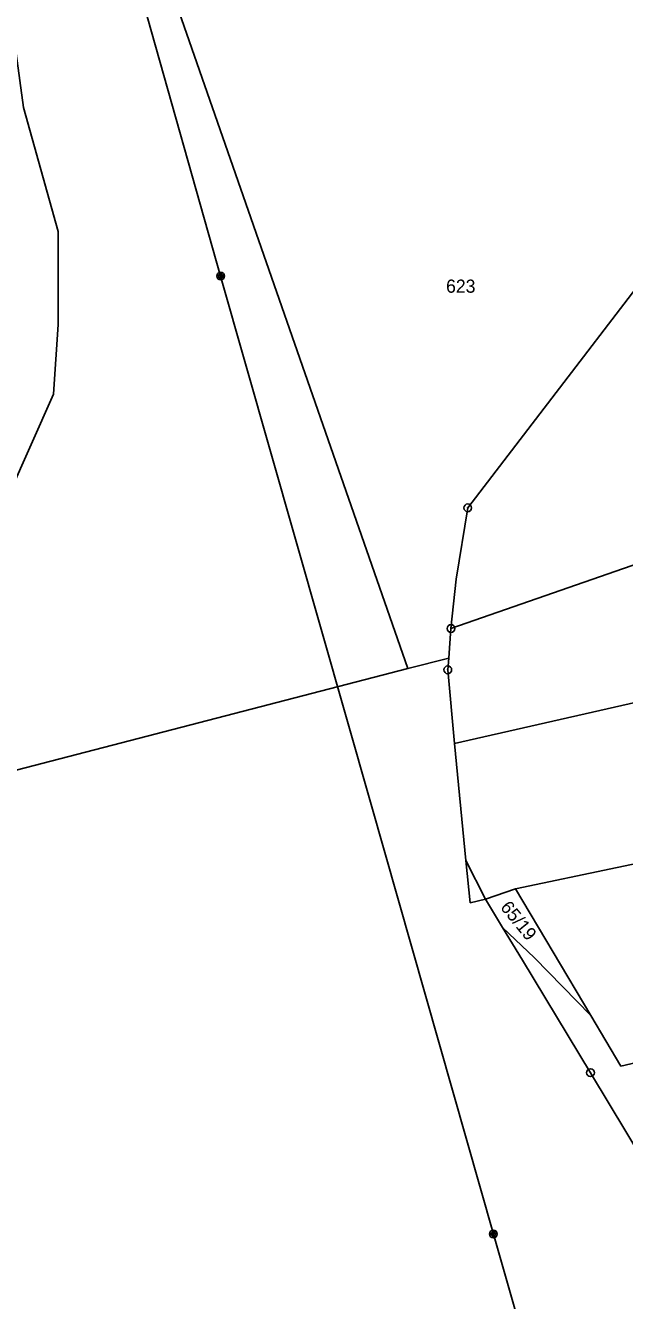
# Model space of a CAD drawing. Extents: x -725765 to -723182, y -1052705 to -1049154.
# Drawn here: x -725049.2 to -724971.9, y -1051081 to -1050916.4 of the extents above; entities that cross this region are included whole.
import ezdxf

# ---------------------------------------------------------------- set-up
doc = ezdxf.new("R2010")
doc.units = 0
for name, color, linetype in [('Vrstva 1', 7, 'Continuous'), ('Vrstva 12', 7, 'Continuous'), ('Vrstva 18', 7, 'Continuous'), ('Vrstva 25', 7, 'Continuous'), ('Vrstva 4', 7, 'Continuous'), ('Vrstva 52', 7, 'Continuous')]:
    doc.layers.add(name, color=color, linetype=linetype)

msp = doc.modelspace()

# ---------------------------------------------------------------- linework, layer by layer
at = {"layer": 'Vrstva 1'}
for points in [[(-725031.43, -1050908.84), (-724999.85, -1050999.45)], [(-724959.02, -1050935.48), (-724992.12, -1050978.69)], [(-724994.29, -1050994.27), (-724880.84, -1050954.87)], [(-724992.12, -1050978.69), (-724993.62, -1050987.89)], [(-724993.62, -1050987.89), (-724994.29, -1050994.27)], [(-724994.29, -1050994.27), (-724994.58, -1050998.09)], [(-724994.58, -1050998.09), (-724999.85, -1050999.45)], [(-724994.58, -1050998.09), (-724994.7, -1050999.6)], [(-724999.85, -1050999.45), (-725199.88, -1051051.31)], [(-724994.7, -1050999.6), (-724993.85, -1051009.11)], [(-724993.85, -1051009.11), (-724952.51, -1050999.73)], [(-724993.85, -1051009.11), (-724992.37, -1051024.21)], [(-724985.97, -1051027.89), (-724946.57, -1051019.61)], [(-724992.37, -1051024.21), (-724991.83, -1051029.69)], [(-724989.82, -1051029.22), (-724985.97, -1051027.89)], [(-724985.97, -1051027.89), (-724976.24, -1051044.24)], [(-724991.83, -1051029.69), (-724989.82, -1051029.22)], [(-724989.82, -1051029.22), (-724987.63, -1051032.85)], [(-724987.63, -1051032.85), (-724983.52, -1051036.79)], [(-724987.63, -1051032.85), (-724985.05, -1051037.1)], [(-724983.52, -1051036.79), (-724976.24, -1051044.24)], [(-724985.05, -1051037.1), (-724976.27, -1051051.61)], [(-724976.24, -1051044.24), (-724972.36, -1051050.76)], [(-724976.27, -1051051.61), (-724964.46, -1051071.2)], [(-724972.36, -1051050.76), (-724970.31, -1051050.31)]]:
    msp.add_lwpolyline(points, dxfattribs=at)
at = {"layer": 'Vrstva 12'}
for points in [[(-725043.92, -1050878.32), (-725024.03, -1050948.77)], [(-725024.03, -1050948.77), (-725004.59, -1051016.98)], [(-725004.59, -1051016.98), (-724988.81, -1051072.44)], [(-724973.47, -1051126.02), (-724988.81, -1051072.44)]]:
    msp.add_lwpolyline(points, dxfattribs=at)
at = {"layer": 'Vrstva 25'}
for centre, radius in [((-725024.03, -1050948.77), 0.5), ((-725024.03, -1050948.77), 0.3), ((-725024.03, -1050948.77), 0.15), ((-724992.12, -1050978.69), 0.5), ((-724992.12, -1050978.69), 0.032), ((-724994.29, -1050994.27), 0.5), ((-724994.29, -1050994.27), 0.032), ((-724994.7, -1050999.6), 0.5), ((-724994.7, -1050999.6), 0.032), ((-724976.27, -1051051.61), 0.5), ((-724976.27, -1051051.61), 0.032), ((-724988.81, -1051072.44), 0.5), ((-724988.81, -1051072.44), 0.3), ((-724988.81, -1051072.44), 0.15)]:
    msp.add_circle(centre, radius, dxfattribs=at)
at = {"layer": 'Vrstva 4'}
msp.add_lwpolyline([(-724992.37, -1051024.21), (-724989.82, -1051029.22)], dxfattribs=at)
at = {"layer": 'Vrstva 52'}
for points in [[(-725222.31, -1051084), (-725204.74, -1051077.08), (-725195.29, -1051073.36), (-725189.31, -1051071), (-725147.13, -1051053), (-725104.19, -1051030), (-725082.38, -1051016), (-725065.81, -1050999), (-725051.38, -1050977), (-725045.63, -1050964), (-725045, -1050955), (-725045, -1050943), (-725049.5, -1050927), (-725051.38, -1050913), (-725049.5, -1050902), (-725045, -1050886), (-725040.9, -1050880.49)], [(-725040.9, -1050880.49), (-725031.43, -1050908.84), (-724999.85, -1050999.45), (-724994.58, -1050998.09), (-724994.29, -1050994.27), (-724993.62, -1050987.89), (-724992.12, -1050978.69), (-724959.02, -1050935.48), (-724959.3, -1050931.91), (-724960.13, -1050921.08), (-724961.29, -1050906.08), (-724961.46, -1050903.95), (-724954.82, -1050902.24)]]:
    msp.add_lwpolyline(points, dxfattribs=at)

# ---------------------------------------------------------------- texts
at = {"layer": 'Vrstva 18'}
msp.add_text('623', height=1.7, dxfattribs=at).set_placement((-724994.92, -1050950.92))
msp.add_text('65/19', height=1.7, rotation=309.1025, dxfattribs=at).set_placement((-724988, -1051030.3))

doc.saveas('drawing.dxf')
